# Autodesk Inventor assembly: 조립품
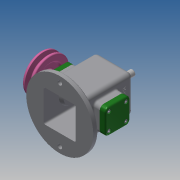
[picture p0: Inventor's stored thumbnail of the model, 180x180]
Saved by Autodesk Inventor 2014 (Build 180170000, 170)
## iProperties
Created: 2021-08
Part Number: 조립품
Document SubType Name: Assembly
Designer: kb542
Author: kb542
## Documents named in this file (16)
- C:\Users\kb542\Desktop\710806V1003\조립품.iam
- C:\Users\kb542\Desktop\710806V1003\본체.ipt
- C:\Users\kb542\Desktop\710806V1003\편심축.ipt
- C:\Users\kb542\Desktop\710806V1003\키 4x4x10.ipt
- C:\Users\kb542\Desktop\710806V1003\V벨트풀리.ipt
- C:\Users\kb542\Desktop\710806V1003\멈춤나사 M3x8.ipt
- C:\Users\kb542\Desktop\710806V1003\슬라이드.ipt
- C:\Users\kb542\Desktop\710806V1003\링크.ipt
- C:\Users\kb542\Desktop\710806V1003\부시.ipt
- C:\Users\kb542\Desktop\710806V1003\핀 5x18.ipt
- C:\Users\kb542\Desktop\710806V1003\고정핀 1.2x8.ipt
- C:\Users\kb542\Desktop\710806V1003\뒤커버.ipt
- C:\Users\kb542\Desktop\710806V1003\앞커버.ipt
- C:\Users\kb542\Desktop\710806V1003\오일 실 12 25 7.ipt
- C:\Users\kb542\Desktop\710806V1003\베어링 12x32x10.ipt
- C:\Users\kb542\Desktop\710806V1003\볼트 M4.ipt
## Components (3 placed, 3 different names)
1. V벨트풀리:1 — 각도:1
2. 핀 5x18:1 — 각도:2
3. 고정핀 1.2x8:1
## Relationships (2: Angle 2)
- 각도:1 [Angle]: V벨트풀리:1
- 각도:2 [Angle]: 핀 5x18:1
